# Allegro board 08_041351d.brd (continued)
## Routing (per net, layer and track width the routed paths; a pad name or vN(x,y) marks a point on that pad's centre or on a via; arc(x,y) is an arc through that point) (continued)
VCC-1P35: length 46
  TOP w0.356: C95.1 49.74,19.48 v1(49.63,19.59) ; v1(43.23,40.33) 43.23,40.34 C117.1 ; v1(42.43,38.73) 42.35,38.65 C118.1 ; C116.1 47.87,40.23 v1(47.99,40.36) ; v1(49.63,36.27) 49.78,36.11 C112.1 ; C92.1 49.65,29.89 v1(49.6,29.94) ; C97.1 42.34,19.48 v1(42.43,19.57) ; C94.1 49.78,23.41 v1(49.63,23.57) ; v1(49.63,37.93) 49.71,38.02 C109.1 ; v1(42.43,21.97) 42.35,21.89 C96.1 ; v1(48.83,17.94) 48.88,17.88 C91.1 ; v1(42.43,36.33) 42.34,36.24 C115.1 ; C120.1 v1(41.71,47.48)
  TOP w0.381: 46.34,37.32 v1(45.65,37.32)
  TOP w0.406: C87.1 50.15,28.37 v1(49.63,28.37) ; C86.1 v1(46.66,22.33) ; v1(41.71,48.88) 41.31,48.88 41.06,48.62 R134.2 ; v1(47.8,60.69) v1(48.31,60.69) ; C106.1 v1(45.65,39.73) ; C108.1 v1(45.65,34.91) ; C88.1 v1(45.65,19.41)
  TOP w0.508: 47.3,25.13 v1(46.41,26.02)
  TOP w0.762: C89.1 47.3,25.13
  L15_SIGNAL w0.508: v2(57.08,14.84) v2(57.84,14.84)
  L15_SIGNAL w0.635: v2(57.08,14.84) v2(56.31,14.84) 53.9,14.84 52.88,15.86 49.96,15.86 48.83,16.99 v1(48.83,17.94)
  BOTTOM w0.356: v1(48.83,17.94) 48.83,17.97 U2.A8 ; v1(49.63,36.27) 49.63,36.33 U3.C9 ; v1(43.23,35.59) 43.29,35.59 U3.B2 ; v1(49.63,37.19) 49.56,37.19 U3.D9 ; U2.R9 v1(49.6,29.94) ; U3.A8 48.57,34.98 v1(48.57,34.73) ; v1(49.7,45.05) 49.65,45 49.64,45 49.37,44.73 U3.N9 ; U3.E9 v1(49.63,37.93) ; U2.H9 v1(49.63,23.57) ; v1(43.23,37.07) 43.23,37.13 U3.D2 ; U2.R1 v1(42.43,29.97) ; v1(42.43,28.3) 42.49,28.3 U2.N1 ; U3.R1 v1(42.43,46.73) ; U3.A1 42.43,34.73 v1(42.43,34.67) ; v1(49.84,46.72) 49.82,46.73 49.63,46.73 U3.R9 ; U3.K8 48.83,42.73 v1(48.83,42.83) ; U2.H2 v1(43.23,23.57) ; v1(47.99,40.36) 47.99,40.3 U3.G7 ; U2.N9 v1(49.63,28.37) ; U2.C9 49.6,19.59 v1(49.63,19.59) ; U3.N1 v1(42.43,45.13) ; U3.C1 v1(42.43,36.33) ; U3.H9 v1(49.63,40.33) ; U3.H2 v1(43.23,40.33) ; U2.B2 v1(43.23,18.77) ; U3.K2 v1(43.23,42.73) ; U2.K2 v1(43.23,25.97) ; U2.E9 v1(49.63,21.17) ; U2.C1 v1(42.43,19.57) ; U3.F1 v1(42.43,38.73) ; U2.K8 v1(48.83,25.97) ; U2.A1 v1(42.43,17.97) ; U2.D2 v1(43.23,20.37) ; U2.D9 v1(49.63,20.37) ; U2.F1 v1(42.43,21.97) ; U2.G7 v1(48.03,22.77)
  vias: v1(47.8,61.2) v1(48.31,61.2) v1(53.14,59.67) v1(53.14,59.04) v1(53.14,58.4) v1(53.14,57.77)
VCC-3P3V: length 7.2
  TOP w0.508: E7.2 23.17,59.54 v1(22.53,60.18) 21.86,59.51 C196.1
  BOTTOM w0.203: R221.1 44.46,60.22 44.5,60.22 ; U14.10 45.39,60.22
  BOTTOM w0.254: 45.39,60.22 44.5,60.22
  BOTTOM w0.381: C43.2 v1(45.52,61.2)
  BOTTOM w0.508: v1(42.47,60.31) R222.1 R221.1 ; R178.1 v1(11.86,55.1)
VCC-3P3V-IO: length 83.8
  TOP w0.127: U1.T6 v1(24.34,34.59) ; U1.K6 v1(29.94,34.59) ; U1.R6 v1(25.14,34.59) ; U1.N6 v1(26.74,34.59)
  TOP w0.305: R168.1 v1(34.98,48.62) ; U11.21 7.55,11.54 7.16,11.16 v1(7.16,10.52) ; U15.21 19.8,52.69 19.61,52.88 v1(19.61,53.07) 19.73,53.19 U15.20 ; U11.17 v1(4.64,13.84) ; R167.1 v1(33.33,48.62)
  TOP w0.381: E8.2 31.23,58.59 31.04,58.4 v1(31.04,57.77)
  TOP w0.406: v1(28.75,40.49) 28.75,41.04 C71.1 29.77,41.04 v1(29.77,40.49) ; R169.2 v1(33.83,43.8) ; J3.4 v1(1.98,27.26) ; v1(6.66,10.01) v1(6.66,10.52) v1(7.16,10.52) ; v2(40.06,49.62) 40.31,49.88 40.31,50.36 D4.A
  TOP w0.508: R8.1 42.47,11.54 41.84,10.9 v1(41.84,8.87) ; C41.1 v1(7.16,10.52) ; C197.1 v2(27.99,58.87)
  L3_SIGNAL w0.406: v1(33.83,43.8) 33.33,44.3 v1(33.33,48.62)
  L7_SIGNAL w0.406: v1(41.84,8.87) 41.84,8.24 41.25,7.65 41.23,7.65 40.96,7.38 40.96,6.22 35.79,1.05 27.31,1.05 25.33,3.03 18.47,3.03 16.82,4.68 10.34,4.68 8.18,6.84 8.18,9.51 v1(7.16,10.52)
  L15_SIGNAL w0.406: v1(34.98,48.62) 37.71,48.62 38.72,49.64 40.04,49.64 v2(40.06,49.62)
  BOTTOM w0.406: v1(29.77,40.49) 29.77,41.13 29.35,41.55 C71.1 29.05,41.55 28.75,41.26 v1(28.75,40.49) ; v2(3.23,10.4) 3.74,10.9
  BOTTOM w0.508: 3.74,10.9 R109.1 ; C57.1 v1(3.23,9.25) ; R4.1 v1(3.61,17) C42.1 ; v1(19.61,53.07) 20.03,53.49 C184.1
VCC-BRAM: length 25.2
  TOP w0.127: U1.H10 v1(31.54,31.39) ; U1.G11 v1(32.34,29.79)
  TOP w0.406: v2(54.41,20.56) 55.04,20.56 C56.1 55.68,19.79 55.04,19.16 v2(54.41,19.16) ; v1(39.93,21.57) 40.63,21.57
  L16_SIGNAL w0.406: v2(54.41,20.56) v2(54.41,19.16) 54.92,18.65 54.92,12.94 54.41,12.43 54.41,10.52 54.79,10.14 54.79,9.25 54.03,8.49 54.03,7.47 54.54,6.97 54.54,4.43 v2(54.66,4.3) ; v2(54.66,4.3) v2(55.3,4.3) 55.3,4.05 v2(54.92,3.66) 54.66,3.92 v2(54.66,4.3)
  BOTTOM w0.406: 39.3,21.57 v1(39.93,21.57)
VCCINT-1P0V: length 11.7
  TOP w0.356: U1.H12 v1(31.54,28.99) ; U1.P12 v1(25.94,28.99) ; U1.M12 v1(27.54,28.99) ; U1.L13 v1(28.34,28.19) ; U1.J13 v1(30.74,28.19) ; U1.R13 v1(25.14,28.19) ; U1.G13 v1(32.34,28.19) ; U1.K12 v1(29.94,28.99) ; U1.N13 v1(26.74,28.19)
  TOP w0.406: C141.1 v1(34.72,20.56) ; C23.1 v1(28.63,20.56) ; C19.1 v1(36.25,20.56)
  BOTTOM w0.406: C141.1 v1(35.49,19.79) ; C23.1 v1(29.39,19.79) ; v1(34.85,16.75) 34.89,16.71 C195.1 ; C16.1 v1(27.74,19.79)
  vias: v1(28.5,16.75) v1(29.64,16.75) v1(30.91,16.75) v1(35.61,16.75)
VCCO-DDR: length 10.2
  TOP w0.356: U1.P2 v1(25.94,37.79) ; U1.L3 v1(28.34,36.99) ; U1.G1 v1(32.34,38.59) ; v1(23.53,38.59) 23.93,38.19 U1.U1 ; U1.E5 v1(33.94,35.39) ; U1.H4 v1(31.54,36.19) ; U1.V4 v1(22.74,36.19) ; U1.D2 v1(34.74,37.79) ; U1.R5 v1(25.14,35.39) ; U1.A3 v1(37.14,36.99)
  TOP w0.406: 49.33,1.51 49.49,1.34 C193.1
  TOP w0.508: E2.2 v1(49.52,4.11)
  BOTTOM w0.406: C17.1 v1(25.96,41.76) ; C11.1 v1(32.06,41.76) ; C121.1 v1(34.72,41.76) ; C125.1 v1(38.15,41.76) ; C20.1 v1(23.29,41.76)
  vias: v1(49.46,4.68)
VCCPCOM-1P8V: length 57.9
  TOP w0.305: v1(24.94,49.89) 24.66,50.17 U15.32 ; U15.28 v1(22.66,49.77) ; U15.14 22.16,56.1 ; U15.11 v1(23.66,56.1) ; v1(67.62,52.81) v1(67.62,53.42) 68.12,53.92 68.12,55.13 U13.B4 ; U11.5 v1(10.58,15.34) ; U15.30 v1(23.66,49.78) ; v1(25.96,54.97) 25.68,54.69 U15.8
  TOP w0.356: U1.B6 v1(36.34,34.59) ; U1.F8 v1(33.14,32.99) ; U1.H8 v1(31.54,32.99) ; U1.K8 v1(29.94,32.99) ; U1.G9 v1(32.34,32.19) ; U1.M8 v1(27.54,32.99) ; U1.D12 v1(34.74,28.99) ; v1(36.34,25.79) U1.B16 ; U1.N11 v1(26.74,29.79) ; U1.J11 v1(30.74,29.79) ; U1.A13 v1(37.14,28.19) ; U1.E15 v1(33.94,26.59) ; U1.N9 v1(26.74,32.19) ; U1.R9 v1(25.14,32.19) ; U1.L11 v1(28.34,29.79) ; U1.P10 v1(25.94,31.39) ; U1.D7 v1(34.74,33.79)
  TOP w0.381: v1(10.58,15.34) 10.75,15.17 11.15,15.17 C54.1
  TOP w0.406: C39.1 46.14,4.06 v1(46.14,4.81) Y1.4 ; R37.1 v1(40.06,22.97) ; C53.1 v1(36.25,41.76) ; C179.1 v1(24.69,41.76) ; L12.1 v1(34.24,45.8) ; C175.1 v1(27.36,41.76) ; R194.1 v1(43.36,13.32)
  TOP w0.508: E9.2 14.53,15.16 v1(14.53,15.98) v1(14.53,16.75) ; v1(47.42,52.81) 48.19,52.81 48.48,52.52 S4.3 ; R9.1 v1(22.66,49.09) ; v1(53.65,52.81) 53.94,52.52 S3.3 ; v1(43.11,4.43) 42.6,4.93 R7.1 42.04,5.75 Q5.1 ; C54.1 C55.1 ; E1.1 v1(26.15,49.19)
  TOP w1.27: S1.3 v2(4.45,7.81)
  BOTTOM w0.254: v1(55.3,61.2) 55.3,61.13 C83.1
  BOTTOM w0.305: C83.1 54.73,61.13 v1(54.66,61.2) ; v1(34.74,33.79) 34.82,33.7
  BOTTOM w0.381: v1(24.94,49.89) 24.94,50.4
  BOTTOM w0.406: C32.1 23.66,48.85 v1(23.66,49.78) ; 54.73,57.32 54.24,57.32 v1(54.23,57.31) ; 54.73,57.32 C82.1 ; 54.73,57.32 v1(54.74,57.31) ; 34.82,33.7 R31.1 ; C174.1 v1(38.41,19.79) ; v1(22.66,49.09) 22.66,48.58 C182.1 ; v1(14.53,16.75) v1(14.53,15.98) ; C52.1 v1(37.01,19.79)
  BOTTOM w0.508: v1(65.97,59.8) R28.1 ; 62.28,48.24 v1(62.28,47.61) ; v1(6.28,28.94) 5.26,28.94 4.62,28.3 R36.1 ; R6.1 v1(51.87,60.81) ; R40.1 45.65,4.31 v1(46.14,4.81)
  BOTTOM w0.635: v1(16.56,36.56) 16.44,36.68 C145.2 17.54,38.25 v1(17.96,37.83) ; C181.1 24.94,51.71 24.94,50.4 ; C126.1 v2(19.7,57.55)
  vias: v1(17.96,37.19) v1(21.96,56.24) v1(25.71,55.73) v2(61.65,45.83)
VCCPINT-1P0V: length 11.8
  TOP w0.356: U1.G7 v1(32.34,33.79) ; U1.N7 v1(26.74,33.79) ; U1.R7 v1(25.14,33.79) ; U1.L7 v1(28.34,33.79) ; U1.J7 v1(30.74,33.79) ; U1.P8 v1(25.94,32.99)
  TOP w0.381: C159.1 40.57,35.03 v1(39.93,35.03)
  TOP w0.406: C163.1 v1(39.93,32.11) ; C10.1 v1(39.93,33.89)
  BOTTOM w0.406: C162.1 v1(39.93,35.03)
  BOTTOM w0.508: v1(77.27,3.54) 78.16,2.65 79.05,2.65 C173.1 78.28,4.43 77.65,4.43 v1(77.52,4.3)
  vias: v2(47.17,9.51) v2(47.93,9.51) v2(56.19,8.11) v2(56.95,8.11) v2(57.71,8.11)
VDD_INTERFACE: length 17.8
  TOP w0.127: U17.H12 v1(66.8,34.49)
  TOP w0.254: U22.1 56.94,29.79 57.43,29.31 v1(57.46,29.31)
  TOP w0.305: R306.2 v1(85.27,7.6) ; C245.1 57.39,28.89 57.44,28.93 57.44,29.28 v1(57.46,29.31)
  TOP w0.356: U1.C19 v1(35.54,23.39) ; U1.K20 v1(29.94,22.59) ; U1.F18 v1(33.14,24.19) ; U1.H14 v1(31.54,27.39) ; 30.34,25.39 v1(30.74,24.99) ; U1.M16 v1(27.54,25.79)
  TOP w0.406: C44.1 v1(31.68,20.56) ; C47.1 v1(33.2,20.56) ; C51.1 v1(30.15,20.56) ; v2(85.02,6.2) E10.2 v2(84.25,5.57) ; U1.J17 30.34,25.39
  TOP w0.508: v1(38.28,14.59) 38.79,14.59 39.42,13.95 C28.1 39.8,13.95 ; v1(41.07,13.44) 40.44,13.44 39.93,13.95 39.8,13.95 ; 39.8,13.95 40.31,14.46 v1(41.07,14.46)
  BOTTOM w0.254: C355.1 66.13,34.97 66.57,34.53 66.76,34.53 v1(66.8,34.49) 66.85,34.55 C356.1
  BOTTOM w0.406: C44.1 v1(32.4,19.79) ; C51.1 v1(30.91,19.79) ; C47.1 v1(33.92,19.79)
  vias: v1(61.27,22.9) v1(61.27,22.4) v1(61.77,22.9) v1(61.77,22.4)
VDDA_GPO: length 5
  TOP w0.127: U17.B8 v1(61.2,31.29)
  BOTTOM w0.305: R67.1 77.65,38.21 v1(77.52,38.08)
  BOTTOM w0.356: v1(61.2,31.29) C319.1 61.04,30.69 C360.1
  BOTTOM w0.508: C358.1 v2(86.54,56.75) ; v2(85.9,55.99) 85.27,56.62 E11.2 ; C361.1 v2(86.54,58.4)
VDDA_GPO_PWR: length 80.3
  TOP w0.406: v2(86.29,6.2) E10.1 v2(87.05,5.57)
  L16_SIGNAL w0.635: 87.05,6.33 88.06,7.35 90.73,7.35 91.37,7.98 91.37,9.51 92.25,10.4 92.25,12.49 91.24,13.51 91.24,33.89 91.87,34.53 91.87,45.13 90.1,46.91 v2(90.1,51.1) v2(90.1,51.92) ; 87.05,6.33 v2(87.05,5.57) ; 87.05,6.33 86.92,6.2 v2(86.29,6.2)
  BOTTOM w0.254: U6.2 81.46,58.14 81.69,58.38 81.42,58.64 U6.1
  BOTTOM w0.406: 85.24,58.74 E11.1
  BOTTOM w0.508: 87.57,47.37 JX4.9 ; 85.24,58.74 C200.1 82.89,58.4 82.88,58.4 82.85,58.38 81.69,58.38
  BOTTOM w0.635: 87.57,47.37 88.78,47.37 90.1,48.69 v2(90.1,51.1) v2(90.1,51.92) 90.1,51.99 90.6,52.5 90.6,58.66 89.59,59.67 86.22,59.67 E11.1
1P3_SUPPLY_A: length 54.5
  TOP w0.305: 79.99,12.61 v1(80.06,12.61) 80.26,12.41
  TOP w0.356: U17.J3 v1(67.6,26.49) ; U17.K3 v1(68.4,26.49) ; U17.B9 v1(61.2,32.09) ; U17.E2 v1(63.6,25.69) ; U17.B10 v1(61.2,32.89) ; U17.F2 v1(64.4,25.69)
  TOP w0.381: v1(77.27,9.63) 77.01,9.38 C315.1 ; v1(77.27,9.63) 77.61,9.97 U19.13 ; v1(77.27,9.63) 76.82,10.08 C314.1 ; v1(77.27,9.63) 77.58,9.32 U19.14 ; v1(78.5,12.72) 78.96,12.26 U19.12 ; U19.11 79.61,12.23 79.99,12.61 ; 81.33,11.53 80.91,11.11 U19.9 ; U19.10 80.26,12.41
  TOP w0.508: C312.1 81.17,12.59 ; 81.17,12.59 81.33,12.43 81.33,11.53 81.71,11.15 v1(81.71,10.65) ; 81.17,12.59 81.15,12.61 v1(80.06,12.61) ; C313.1 v1(78.5,12.72)
  TOP w0.635: v2(79.48,47.5) v1(78.82,47.5) 78.03,46.72 74.22,46.72 73.39,47.54 67.55,47.54 65.08,45.07 65.08,39.86 v1(61.01,35.8)
  BOTTOM w0.33: U24.18 78.94,44.94 79.48,45.47 79.48,46.57
  BOTTOM w0.356: C329.1 68.24,26.33 v1(68.4,26.49) ; v1(64.4,25.69) 64.28,25.57 C322.1 63.72,25.57 v1(63.6,25.69) ; v1(61.2,32.89) 61.33,32.76 C321.1 61.33,32.23 v1(61.2,32.09) ; C326.1 67.44,26.33 v1(67.6,26.49)
  BOTTOM w0.406: C327.1 v1(61.01,35.8) ; C323.1 69.68,22.42 v2(69.68,22.99) 69.68,23.58 C320.1
  BOTTOM w0.508: v2(68.12,22.84) 68.12,22.08 C328.1
  BOTTOM w0.635: v1(78.82,47.5) v2(79.48,47.5) 79.48,46.57
1P3_SUPPLY_B: length 67.5
  TOP w0.254: 86.79,10.4 v1(86.92,10.27) ; 86.79,9.63 v1(86.92,9.51)
  TOP w0.305: L1.1 v1(68.88,35.87) ; 89.91,11.86 v1(90.26,12.21)
  TOP w0.356: C343.1 86.79,10.4 ; C344.1 86.79,9.63 ; U17.A9 v1(60.4,32.09) ; U17.K4 v1(68.4,27.29) ; U17.A8 v1(60.4,31.29) ; U17.F12 v1(64.4,34.49) ; U17.D3 v1(62.8,26.49) ; U17.A7 v1(60.4,30.49) ; U17.E3 v1(63.6,26.49) ; U17.D2 v1(62.8,25.69) ; v1(60.4,32.89) U17.A10
  TOP w0.381: U20.13 87.22,9.97 v1(86.92,10.27) ; L9.1 v1(71.74,28.74) ; v1(90.26,12.21) 90.56,11.91 U20.9 ; U20.12 88.61,11.75 v1(88.32,12.05) 88.28,12.08 ; U20.14 87.1,9.32 v1(86.92,9.51) ; L8.1 71.3,31.45 v1(71.3,31.73) ; L2.1 v1(72.49,35.87) ; U20.10 89.91,11.86 ; U20.11 v1(89.26,11.99)
  TOP w0.508: C341.1 v1(90.26,12.21) ; C342.1 88.28,12.08
  L9_POWER w0.203: v1(64.4,34.49) 64.4,35.08 v1(63.68,35.8) ; 61.77,39.48 61.77,36.3 v1(62.28,35.8) 61.77,35.29 61.27,35.29 60.79,34.81 60.79,33.29 v1(60.4,32.89) v1(60.4,32.09) ; 63.2,21.98 63.2,25.29 v1(62.8,25.69) v1(62.8,26.49) ; 64.19,21.95 64.19,24.3 64,24.49 64,26.09 v1(63.6,26.49) ; v1(59.23,27.54) 59.23,29.33 v1(60.4,30.49) v1(60.4,31.29) ; v1(68.4,27.29) 68.38,27.29 68,26.91 68,25.38 67.77,25.15 v2(67.77,24.64)
  L9_POWER w0.254: 63.3,39.35 63.3,36.18 v1(63.68,35.8) ; 62.66,21.57 60.06,21.57 59.23,22.4 v1(59.23,27.54) ; v2(67.77,24.64) 67.77,24.09 69.52,22.33
  BOTTOM w0.254: C330.1 64.43,34.53 v1(64.4,34.49)
  BOTTOM w0.33: U24.19 79.36,44.44 80.11,45.19 v1(80.11,45.32)
  BOTTOM w0.356: C334.1 62.67,26.37 v1(62.8,26.49) ; C325.1 60.38,30.47 v1(60.4,30.49) ; v1(68.4,27.29) 68.4,27.27 C333.1
  BOTTOM w0.406: C335.1 v1(63.68,35.8) ; C332.1 v1(62.28,35.8)
  BOTTOM w0.508: C324.1 68,23.92 68,24.42 v2(67.77,24.64)
  BOTTOM w0.635: 58.47,27.54 v1(59.23,27.54)
  vias: v1(74.16,29.76) v1(74.16,29.32) v1(74.6,29.76) v1(74.6,29.32) v2(65.97,37.07) v2(66.6,37.07) v2(67.24,37.07)
AD9364_CLK: length 48.4
  TOP w0.14: C62.1 74.16,57 v1(73.84,57)
  L16_SIGNAL w0.095: v1(89.9,29.76) 90.48,30.33 90.48,33.95 88.51,35.92 88.51,44.11 89.33,44.94 89.33,45.76 88.9,46.2 88.9,50.17 87.45,51.62 82.27,51.62 77.9,55.99 74.86,55.99 v1(73.84,57)
  BOTTOM w0.14: v1(73.84,57) 73.27,57 R5.1 ; v1(89.9,29.76) 89.59,29.45 89.59,27.59 87.77,25.77 JX4.63
ADP2114_VIN: length 8.2
  TOP w0.305: v2(72.32,2.52) 71.05,2.52 70.09,3.48 U4.10 ; U4.8 68.73,1.66 v1(68.89,1.51) 68.82,1.44 R23.2 ; v1(66.85,1.51) 66.73,1.63 U4.4 ; U4.31 v2(63.48,3.48)
  TOP w0.406: C146.1 v2(62.41,1.89) ; C150.1 v2(62.66,2.9)
AUXADC: length 34.8
  TOP w0.127: U17.L5 v1(69.2,28.09)
  L16_SIGNAL w0.095: v1(69.2,28.09) 69.56,27.73 73.97,27.73 75.74,29.51 75.74,31.22 78.72,34.2 78.72,35.01 81.71,38.01 81.71,44.49 86.09,48.88 v1(87.3,48.88)
  BOTTOM w0.14: v1(87.3,48.88) 87.3,48.35 87.12,48.17 JX4.7
AUXDAC1: length 38.8
  TOP w0.127: U17.B3 v1(61.2,26.49)
  L16_SIGNAL w0.095: v1(61.2,26.49) 61.2,26.47 61.52,26.14 62.16,26.14 62.46,26.45 62.46,26.63 62.66,26.83 62.84,26.83 62.89,26.88 64.92,26.88 65.46,27.41 65.46,28.18 65.76,28.48 70.27,28.48 70.66,28.87 70.66,29.45 72.7,31.48 72.7,33 73.9,34.21 75.74,34.21 77.09,35.55 77.09,36.33 77.97,37.21 77.97,38.53 81.27,41.83 81.27,46.46 v1(82.98,48.17)
  BOTTOM w0.14: JX4.8 v1(82.98,48.17)
AUXDAC2: length 36.1
  TOP w0.127: U17.C3 v1(62,26.49)
  L16_SIGNAL w0.095: v1(62,26.49) 62,26.77 62.36,27.13 62.36,27.46 62.59,27.69 64.72,27.69 65.08,28.05 65.08,28.56 65.84,29.32 70.03,29.32 72.32,31.6 72.32,33.26 73.78,34.72 74.86,34.72 77.14,37 77.14,39.61 79.3,41.76 80.44,41.76 80.82,42.15 80.82,47.02 v1(80.24,47.61)
  BOTTOM w0.14: v1(80.24,47.61) 80.57,47.61 80.81,47.37 JX4.10
CARRIER_RESET: length 64.3
  TOP w0.14: Q5.3 42.98,10.01 43.87,10.9 R8.2 v1(43.87,12.43)
  L3_SIGNAL w0.095: v1(32.73,49.55) 33.45,50.27 37.72,50.27 39.75,48.24 44.63,48.24 45,47.87 46.52,47.87 46.99,48.34 49.4,48.34 49.89,47.86 v1(50.47,47.86)
  L16_SIGNAL w0.095: v1(43.87,12.43) 46.28,12.43 46.79,12.94 46.79,17.63 47.68,18.52 48.1,18.52 48.69,19.1 48.89,19.1 49.07,19.29 49.45,19.29 49.49,19.25 49.93,19.25 50.47,19.79 v1(50.47,47.86)
  BOTTOM w0.14: JX1.6 v1(32.73,49.55)
COMP_1P8V: length 6.6
  TOP w0.14: U4.2 65.73,1.91 65.33,1.51 v1(65.33,1)
  BOTTOM w0.14: v1(65.33,1) 62.39,1 62.14,1.25 R46.1 C67.1
COMP_1P35V: length 3.7
  TOP w0.14: U4.7 v1(68.23,1.31)
  BOTTOM w0.14: v1(68.23,1.31) 68.44,1.53 68.44,2.08 C68.1 69.14,2.01 C114.1
CTRL_IN0: length 5.8
  TOP w0.127: U17.C5 v1(62,28.09)
  TOP w0.14: v1(58.73,30.21) 58.46,30.48 U22.2
  L12_SIGNAL w0.095: v1(62,28.09) 61.66,28.43 60.12,28.43 58.73,29.83 v1(58.73,30.21)
CTRL_IN1: length 6.8
  TOP w0.127: U17.C6 v1(62,28.89)
  TOP w0.14: U22.3 58.59,30.98 v1(58.73,30.84)
  L12_SIGNAL w0.095: v1(58.73,30.84) 58.73,30.97 58.98,31.22 59.99,31.22 60.26,30.95 61.06,30.95 61.98,30.03 62.14,30.03 62.34,29.83 62.34,29.23 v1(62,28.89)
CTRL_IN2: length 6.9
  TOP w0.127: U17.D5 v1(62.8,28.09)
  TOP w0.14: U22.4 58.6,31.48 59.09,30.99 59.09,30.99 v1(59.23,30.84)
  L12_SIGNAL w0.095: v1(59.23,30.84) 59.36,30.84 60.38,29.83 60.89,29.83 61.66,29.05 61.66,28.75 61.75,28.66 61.98,28.43 62.14,28.43 62.48,28.09 v1(62.8,28.09)
CTRL_IN3: length 7.6
  TOP w0.127: U17.D6 v1(62.8,28.89)
  TOP w0.14: U22.5 v1(58.72,31.98)
  L12_SIGNAL w0.095: v1(58.72,31.98) 59.75,31.98 60.1,31.63 61.34,31.63 61.54,31.43 61.54,31.15 61.86,30.83 62.14,30.83 62.34,30.63 62.34,30.28 62.79,29.83 62.79,28.9 v1(62.8,28.89)
DDR3_A0: length 57.7
  TOP w0.197: R136.1 45.2,45.45 44.34,45.45 v1(44.03,45.13) ; U1.N2 v1(26.74,37.79)
  L6_SIGNAL w0.14: v1(44.03,45.13) 44.5,44.65 44.5,44.29 44.18,43.97 43.95,43.97 43.66,43.68 43.66,43.46 43.38,43.17 43.11,43.17 42.85,42.91 42.85,35.41 43.24,35.03 43.38,35.03 43.59,34.82 43.59,34.17 45.72,32.04 45.72,29.65 44.37,28.3 v1(44.03,28.3)
  L7_SIGNAL w0.14: v1(44.03,28.3) 47.3,28.3 47.68,27.92 47.4,26.89 47.31,26.61 47.07,26.4 41.07,26.4 40.31,27.16 40.31,27.16 37.76,29.71 37.76,30.09 37.44,30.42 31.04,30.42 30.3,31.16 30.3,31.54 30.09,31.75 29.66,31.75 28.96,32.45 28.7,32.72 28.7,33.14 28.49,33.35 28.19,33.35 27.9,33.64 27.9,33.94 27.69,34.15 27.39,34.15 27.1,34.44 27.1,34.78 26.85,35.03 26.59,35.03 26.37,35.24 26.37,36.34 26.59,36.55 26.81,36.55 27.07,36.81 27.1,36.81 27.1,37.14 26.74,37.5 v1(26.74,37.79)
  BOTTOM w0.197: U2.N3 44.09,28.3 v1(44.03,28.3) ; U3.N3 v1(44.03,45.13)
DDR3_A1: length 56
  TOP w0.197: U1.K2 v1(29.94,37.79) ; v1(48.03,45.93) 47.17,46.79 47.17,47.21 47,47.38 46.83,47.38 R137.1
  L12_SIGNAL w0.14: v1(48.03,45.93) 47.27,45.93 46.77,45.43 46.51,45.43 46.3,45.22 46.3,44.96 46.2,44.86 46.2,31.06 v1(48.03,29.23)
  L13_SIGNAL w0.14: v1(29.94,37.79) 30.11,37.79 30.47,38.15 30.89,38.15 31.1,37.94 31.1,37.64 31.39,37.35 31.69,37.35 31.9,37.14 31.9,36.84 32.19,36.55 32.49,36.55 32.7,36.34 32.7,36.04 32.99,35.75 33.28,35.75 33.57,35.46 33.57,34.44 33.86,34.15 34.09,34.15 34.37,33.86 34.37,33.64 34.59,33.43 35.39,33.43 36.19,33.43 38.36,33.43 38.38,33.4 38.68,33.4 38.71,33.43 40.57,33.43 40.69,33.55 40.69,33.89 40.82,34.02 41.58,34.02 41.71,33.89 41.71,33.55 41.84,33.43 44.76,33.43 44.88,33.3 44.88,32.87 45.01,32.75 45.52,32.75 45.65,32.62 45.65,32.11 45.52,31.99 45.01,31.99 44.88,31.86 44.88,31.35 44.76,31.22 41.96,31.22 41.71,30.97 41.71,30.21 42.06,29.85 42.06,29.82 42.28,29.6 47.65,29.6 v1(48.03,29.23)
  BOTTOM w0.197: U3.P7 v1(48.03,45.93) ; U2.P7 48.03,29.17 v1(48.03,29.23)
DDR3_A2: length 58.2
  TOP w0.197: v1(44.03,45.87) 44.37,46.21 45.2,46.21 R138.1 ; U1.M3 v1(27.54,36.99)
  L6_SIGNAL w0.14: v1(44.03,29.23) 44.29,29.23 45.19,30.13 45.19,31.42 43.31,33.29 42.6,33.29 41.62,34.27 41.62,42.82 42.22,43.42 42.22,43.42 42.24,43.43 42.61,43.43 43.08,43.89 43.3,43.89 43.66,44.26 43.66,45.28 44.03,45.64 v1(44.03,45.87)
  L13_SIGNAL w0.14: v1(27.54,36.99) 27.54,36.68 27.41,36.56 26.5,36.56 26.37,36.68 26.37,38.88 26.98,39.48 28.37,39.48 29.57,38.28 29.57,36.84 29.86,36.55 30.09,36.55 30.37,36.26 30.37,36.04 30.66,35.75 30.89,35.75 31.17,35.47 31.17,32.75 31.36,32.55 34.09,32.55 34.37,32.26 34.37,32.04 34.59,31.83 37.29,31.83 37.44,31.99 37.9,31.99 38.15,32.24 38.15,32.61 38.28,32.73 38.55,32.73 38.66,32.62 38.66,32.11 38.79,31.99 39.04,31.99 39.17,32.11 39.17,32.61 39.3,32.73 39.49,32.73 39.59,32.64 39.59,32.38 39.47,32.26 39.47,32.06 39.57,31.97 39.57,31.73 39.8,31.5 39.8,30.97 41.2,29.57 41.2,28.43 41.83,27.79 42.14,27.79 42.28,27.93 42.58,27.93 42.71,27.79 42.94,27.79 43.08,27.93 43.1,27.93 43.11,27.94 43.38,27.94 43.59,28.15 43.59,28.4 43.61,28.43 43.61,28.82 v1(44.03,29.23)
  BOTTOM w0.197: v1(44.03,29.23) 44.03,29.17 U2.P3 ; v1(44.03,45.87) 44.09,45.87 U3.P3
DDR3_A3: length 57.7
  TOP w0.197: R139.1 41.21,45.52 42.59,45.52 42.98,45.13 v1(43.23,45.13) ; U1.K3 v1(29.94,36.99)
  L6_SIGNAL w0.14: v1(43.23,28.3) 43.23,28.72 43.59,29.08 43.59,29.11 43.66,29.19 43.66,29.38 43.89,29.6 44.18,29.6 44.92,30.35 44.92,31.3 43.2,33.03 42.33,33.03 41.35,34 41.35,43.03 42.24,43.92 42.6,43.92 42.85,44.18 42.85,44.43 42.86,44.44 42.86,44.48 43.23,44.84 v1(43.23,45.13)
  L13_SIGNAL w0.14: v1(43.23,28.3) 42.91,28.62 42.91,28.75 42.78,28.88 42.65,28.88 42.58,28.8 42.42,28.8 42.04,28.43 41.84,28.43 41.71,28.56 41.71,29.57 41.2,30.08 41.2,30.84 41.07,30.97 40.44,30.97 40.31,31.1 40.31,31.35 40.57,31.6 40.57,32.49 40.69,32.62 41.71,32.62 41.84,32.49 41.84,31.86 42.09,31.6 42.85,31.6 42.98,31.73 42.98,32.49 43.11,32.62 43.61,32.62 43.74,32.49 43.74,31.73 43.87,31.6 44.12,31.6 44.38,31.86 44.38,32.75 44.12,33 38.15,33 37.77,32.62 34.6,32.62 34.59,32.63 34.59,32.63 34.37,32.84 34.37,33.06 34.09,33.35 32.19,33.35 31.9,33.64 31.9,35.54 31.61,35.83 31.39,35.83 31.17,36.04 31.17,36.76 31.1,36.84 31.1,37.14 30.89,37.35 30.31,37.35 29.95,36.99 v1(29.94,36.99)
  BOTTOM w0.197: v1(43.23,28.3) 43.29,28.3 U2.N2 ; U3.N2 v1(43.23,45.13)
DDR3_A4: length 56.3
  TOP w0.197: v1(48.83,45.93) 49.22,46.33 50.16,46.33 R140.1 ; U1.M4 v1(27.54,36.19)
  L6_SIGNAL w0.14: v1(48.83,29.23) 49.18,29.58 49.75,29.58 49.96,29.79 49.96,29.95 51.88,31.87 51.88,39.48 52.84,40.43 52.84,43.21 52.01,44.03 52.01,44.03 49.99,46.06 49.99,46.08 49.78,46.29 49.75,46.29 49.71,46.34 49.23,46.34 v1(48.83,45.93)
  L7_SIGNAL w0.14: v1(48.83,29.23) 48.44,29.62 48.44,31.1 48.69,31.35 49.58,31.35 49.84,31.6 49.84,33.38 49.12,34.1 45.44,34.1 45.27,34.27 42.22,34.27 40.29,36.2 40.29,36.45 39.32,37.43 32.99,37.43 32.7,37.72 32.7,37.94 32.49,38.15 29.71,38.15 29.01,37.45 29.01,36.94 28.62,36.55 28.19,36.55 27.82,36.19 v1(27.54,36.19)
  BOTTOM w0.197: v1(48.83,29.23) 48.83,29.17 U2.P8 ; U3.P8 v1(48.83,45.93)
DDR3_A5: length 59.2
  TOP w0.197: v1(43.23,45.87) 42.76,46.34 R141.1 ; U1.L1 v1(28.34,38.59)
  L6_SIGNAL w0.14: v1(43.23,29.23) 43.23,29.45 43.59,29.82 43.59,30.18 43.81,30.4 44.18,30.4 44.39,30.62 44.39,31.08 42.98,32.49 41.71,32.49 40.82,33.38 40.82,45.19 41.49,45.87 41.98,45.87 42.28,45.57 42.58,45.57 42.87,45.87 v1(43.23,45.87)
  L7_SIGNAL w0.14: v1(28.34,38.59) 27.95,38.97 25.71,38.97 25.69,38.96 24.8,38.96 24.7,38.85 24.7,38.33 24.82,38.21 25.33,38.21 25.45,38.34 25.68,38.34 25.79,38.23 25.82,38.23 25.83,38.21 26.09,38.21 26.21,38.34 26.47,38.34 26.6,38.21 27.74,38.21 27.9,38.05 27.9,36.84 27.61,36.55 27.39,36.55 27.17,36.34 27.17,36.04 27.46,35.75 28.58,35.75 29.39,36.56 29.39,37.07 29.67,37.35 30.89,37.35 31.17,37.06 31.17,36.84 31.46,36.55 31.69,36.55 31.97,36.26 31.97,36.04 32.26,35.75 32.49,35.75 32.77,35.46 32.77,34.32 32.94,34.15 38.91,34.15 39.68,33.38 40.18,33.38 41.44,32.13 41.44,31.74 41.85,31.34 41.85,31.34 41.98,31.21 42.6,31.21 42.79,31.02 42.79,30.52 42.99,30.33 43.46,30.33 43.59,30.2 43.59,29.82 43.23,29.45 v1(43.23,29.23)
  BOTTOM w0.197: v1(43.23,29.23) 43.23,29.17 U2.P2 ; v1(43.23,45.87) 43.29,45.87 U3.P2
DDR3_A6: length 59.1
  TOP w0.197: U1.L4 v1(28.34,36.19) ; R143.1 50.28,47.23 49.87,47.23 49.79,47.14 49.24,47.14 48.9,46.79 v1(48.83,46.79)
  L6_SIGNAL w0.14: v1(48.83,29.9) 49.33,30.4 49.78,30.4 49.9,30.53 49.9,30.53 51.61,32.24 51.61,39.99 51.99,40.36 51.99,40.88 51.61,41.26 51.61,43.46 51.38,43.69 51.08,43.69 50.87,43.9 50.87,44.28 50.06,45.1 50.06,45.2 49.85,45.41 49.11,45.41 48.95,45.57 48.68,45.57 48.46,45.78 48.46,46.43 v1(48.83,46.79)
  L13_SIGNAL w0.14: v1(28.34,36.19) 28.34,35.9 28.75,35.48 28.75,30.46 29.57,29.64 29.57,29.64 29.79,29.43 37.41,29.43 42.85,23.98 47.42,23.98 47.92,24.48 48.18,24.48 48.5,24.8 48.98,24.8 49.19,25.02 49.19,25.49 49.2,25.51 49.2,29.53 v1(48.83,29.9)
  BOTTOM w0.197: U2.R8 48.76,29.9 v1(48.83,29.9) ; U3.R8 48.83,46.73 v1(48.83,46.79)
DDR3_A7: length 58.7
  TOP w0.197: v1(43.23,46.79) 42.84,47.18 42.84,47.75 42.6,47.99 R144.1 ; U1.K4 v1(29.94,36.19)
  L6_SIGNAL w0.14: v1(43.23,29.97) 43.22,29.97 42.78,30.4 42.28,30.4 42.06,30.62 42.06,31.12 39.55,33.64 39.55,42.27 39.31,42.5 39.31,42.8 39.55,43.04 39.55,45.45 39.7,45.59 39.7,45.6 39.91,45.81 39.91,45.81 40.08,45.98 40.21,45.98 41.33,47.1 42.92,47.1 v1(43.23,46.79)
  L7_SIGNAL w0.14: v1(43.23,29.97) 42.83,29.57 41.83,29.57 40.07,31.34 39.94,31.34 39.8,31.48 39.68,31.48 37.99,33.17 37.99,33.35 38.22,33.57 38.4,33.57 39.04,32.93 39.04,32.62 39.17,32.49 39.55,32.49 39.77,32.71 39.97,32.71 40.57,32.11 40.57,31.99 40.31,31.73 40.31,31.6 40.64,31.28 40.69,31.28 41.84,30.14 42.02,30.14 42.19,30.31 42.19,30.49 41.26,31.41 41.26,31.42 41.17,31.51 41.17,32.01 40.12,33.06 39.61,33.06 38.79,33.88 37.76,33.88 37.64,33.76 37.64,33.51 37.52,33.38 37.01,33.38 36.88,33.51 36.57,33.51 36.44,33.38 36.19,33.38 36.06,33.51 35.87,33.51 35.74,33.38 35.43,33.38 35.18,33.64 35.1,33.64 34.85,33.38 34.64,33.38 34.59,33.43 34.59,33.43 34.42,33.6 34.25,33.6 34.09,33.43 34.01,33.43 33.96,33.38 33.83,33.38 33.79,33.43 33.79,33.43 33.58,33.63 33.49,33.63 33.26,33.4 33.26,33.38 33.03,33.38 32.77,33.64 32.77,33.86 32.49,34.15 32.26,34.15 31.97,34.44 31.97,34.78 32.12,34.92 32.12,35.09 31.97,35.24 31.97,35.46 31.69,35.75 31.34,35.75 31.17,35.92 31.17,36.27 30.88,36.56 30.66,36.56 30.59,36.63 30.59,36.63 30.44,36.77 30.24,36.77 30.15,36.68 30.14,36.68 30.09,36.63 29.84,36.63 29.64,36.43 29.64,36.29 29.78,36.15 29.9,36.15 v1(29.94,36.19)
  BOTTOM w0.197: v1(43.23,46.79) 43.23,46.73 U3.R2 ; U2.R2 v1(43.23,29.97)
DDR3_A8: length 57.9
  TOP w0.197: v1(48.83,47.53) 49.2,47.9 49.2,48.3 R145.1 ; U1.K1 v1(29.94,38.59)
  L6_SIGNAL w0.14: v1(48.83,30.83) 48.83,31.1 50.99,33.27 50.99,42.26 49.41,43.84 49.41,43.85 49.04,44.21 47.89,44.21 47.31,44.8 47.31,46.86 47.61,47.15 48.45,47.15 v1(48.83,47.53)
  L7_SIGNAL w0.14: v1(48.83,30.83) 49.32,30.33 50.74,30.33 51.49,31.08 51.49,32.62 51.74,32.87 53.14,32.87 53.27,33 53.27,33.89 53.14,34.02 50.22,34.02 49.84,34.4 48.75,34.4 48.72,34.37 45.55,34.37 44.88,35.03 42.09,35.03 38.91,38.21 33.77,38.21 33.71,38.15 33,38.15 32.7,38.46 32.7,38.74 32.49,38.95 30.3,38.95 v1(29.94,38.59)
  BOTTOM w0.197: U3.T8 v1(48.83,47.53) ; U2.T8 48.83,30.77 v1(48.83,30.83)
DDR3_A9: length 57.6
  TOP w0.197: R146.1 45.14,47.23 44.7,46.79 v1(44.03,46.79) ; U1.J4 v1(30.74,36.19)
  L6_SIGNAL w0.14: v1(44.03,46.79) 43.99,46.76 43.99,46.34 43.89,46.23 43.88,46.23 43.66,46.02 43.66,45.79 43.38,45.5 43.16,45.5 43.15,45.49 43.08,45.49 42.86,45.28 42.86,45.21 42.79,45.13 42.79,44.98 42.58,44.77 42.28,44.77 41.98,45.07 41.33,45.07 41.09,44.83 41.09,33.89 42.22,32.76 43.09,32.76 44.65,31.19 44.65,30.51 44.29,30.14 44.2,30.14 v1(44.03,29.97)
  L7_SIGNAL w0.14: v1(30.74,36.19) 30.74,35.9 31.1,35.54 31.1,34.52 31.46,34.15 31.69,34.15 31.97,33.86 31.97,33.64 32.26,33.35 32.49,33.35 32.77,33.06 32.77,32.84 32.99,32.63 33.19,32.63 33.2,32.62 38.1,32.62 39.65,31.07 39.95,31.07 42.34,28.68 42.89,28.68 43.08,28.87 44.5,28.87 44.63,28.99 44.63,29.7 44.76,29.83 44.98,29.83 45.11,29.7 45.11,28.68 45.22,28.57 45.53,28.57 45.65,28.68 45.65,30.33 45.77,30.46 46.03,30.46 46.15,30.33 46.15,28.81 46.28,28.68 46.79,28.68 46.92,28.81 46.92,29.19 46.66,29.45 46.66,30.08 46.92,30.33 46.92,30.78 46.74,30.96 44.63,30.96 44.5,30.83 44.5,30.08 44.39,29.97 v1(44.03,29.97)
  BOTTOM w0.197: v1(44.03,46.79) 44.03,46.73 U3.R3 ; U2.R3 v1(44.03,29.97)
DDR3_A10: length 53.5
  TOP w0.197: U1.F5 v1(33.14,35.39) ; v1(48.03,43.53) 48.42,43.92 48.57,43.92 48.62,43.98 49.35,43.98 49.46,43.86 49.97,43.86 R147.1
  L7_SIGNAL w0.14: v1(48.03,26.7) 48.53,27.2 49.78,27.2 49.99,27.42 49.99,27.42 50.09,27.52 50.09,28.05 50.34,28.3 50.98,28.3 51.23,28.05 51.23,27.52 51.49,27.27 51.74,27.27 52,27.52 52,28.41 51.74,28.66 49.84,28.66 49.78,28.73 48.02,28.73 47.4,29.35 47.4,30.68 46.85,31.22 43.36,31.22 43.11,31.48 42.09,31.48 41.71,31.86 41.71,32.87 39.91,34.67 39.78,34.67 39.42,35.03 37.29,35.03 37.29,35.03 33.79,35.03 33.42,35.39 v1(33.14,35.39)
  L12_SIGNAL w0.14: v1(48.03,43.53) 48.44,43.12 48.44,41.7 48.53,41.6 48.68,41.45 48.75,41.45 48.96,41.24 49.72,41.24 50.2,40.76 50.2,28.18 49.96,27.93 49.58,27.93 49.58,27.93 49.48,27.93 49.26,27.72 49.26,27.61 49.22,27.57 49.22,27.51 48.98,27.27 48.59,27.27 v1(48.03,26.7)
  BOTTOM w0.152: U3.L7 v1(48.03,43.53)
  BOTTOM w0.197: v1(48.03,26.7) 47.96,26.7 U2.L7
DDR3_A11: length 58.8
  TOP w0.197: R148.1 47.17,48.24 47.55,47.86 47.55,47.27 v1(48.03,46.79) ; U1.G4 v1(32.34,36.19)
  L6_SIGNAL w0.14: v1(48.03,29.9) 48.59,30.47 48.98,30.47 49.19,30.68 49.19,30.96 51.26,33.03 51.26,40.01 51.72,40.47 51.72,40.77 51.26,41.23 51.26,43.14 50.43,43.97 50.43,44.1 49.91,44.61 49.08,44.61 48.95,44.48 48,44.48 47.58,44.91 47.58,46.34 48.03,46.79 v1(48.03,46.79)
  L7_SIGNAL w0.14: v1(48.03,29.9) 47.66,30.26 47.66,30.98 47.68,30.99 47.68,31.48 47.42,31.73 45.77,31.73 45.52,31.99 45.52,33.38 45.39,33.51 45.14,33.51 45.01,33.38 45.01,31.73 44.88,31.6 44.63,31.6 44.5,31.73 44.5,33.5 44.38,33.62 44.12,33.62 43.99,33.5 43.99,31.73 43.87,31.6 43.61,31.6 43.49,31.73 43.49,33.26 43.36,33.38 43.1,33.38 42.85,33.13 42.85,32.49 42.98,32.37 42.98,31.98 42.75,31.75 42.45,31.75 42.09,32.11 42.09,33.17 40.29,34.97 40.29,35.18 40.08,35.39 39.86,35.39 39.51,35.75 38.79,35.75 38.66,35.88 38.66,35.92 38.53,36.05 37.9,36.05 37.77,35.92 37.77,35.88 37.64,35.75 33.06,35.75 32.74,36.07 32.74,37.14 32.53,37.35 32.19,37.35 31.97,37.14 31.97,36.82 32.34,36.46 v1(32.34,36.19)
  BOTTOM w0.197: v1(48.03,46.79) 48.03,46.73 U3.R7 ; U2.R7 47.96,29.9 v1(48.03,29.9)
DDR3_A12: length 51.6
  TOP w0.197: v1(48.03,45.13) 46.79,46.37 46.79,46.65 R149.1 ; U1.E4 v1(33.94,36.19)
  L12_SIGNAL w0.14: v1(48.03,28.3) 48.46,28.74 48.46,30.98 48.57,31.08 48.57,31.99 48.06,32.49 47.3,32.49 47.17,32.62 47.17,39.99 47.28,40.1 47.28,40.4 47.17,40.52 47.17,44.69 47.61,45.13 v1(48.03,45.13)
  L13_SIGNAL w0.14: v1(33.94,36.19) 33.94,36.4 34.08,36.55 34.89,36.55 35.1,36.34 35.1,36.18 35.17,36.11 35.17,35.24 35.39,35.03 38.91,35.03 39.3,35.41 41.58,35.41 41.96,35.03 44.5,35.03 46.79,32.75 49.46,32.75 49.84,32.37 49.84,31.49 49.27,30.92 49.27,30.76 48.98,30.47 48.83,30.47 48.44,30.08 48.44,27.54 48.19,27.29 46.53,27.29 46.28,27.54 46.28,28.05 46.53,28.3 v1(48.03,28.3)
  BOTTOM w0.197: U2.N7 47.96,28.3 v1(48.03,28.3) ; U3.N7 v1(48.03,45.13)
DDR3_A13: length 54.7
  TOP w0.197: R150.1 44.63,48.69 44.63,47.78 44.38,47.53 v1(44.03,47.53) ; U1.D4 v1(34.74,36.19)
  L6_SIGNAL w0.14: v1(44.03,30.77) 44.03,30.81 43.11,31.73 41.84,31.73 40.45,33.12 40.45,43.3 40.55,43.39 40.55,43.69 40.45,43.79 40.45,45.59 41.09,46.23 42.21,46.23 42.28,46.29 42.58,46.29 42.64,46.23 43.17,46.23 43.66,46.72 43.66,46.94 44.03,47.3 v1(44.03,47.53)
  L13_SIGNAL w0.14: v1(44.03,30.77) 44.45,30.77 45.26,29.95 47.17,29.95 47.42,30.21 47.42,30.46 47.17,30.72 45.52,30.72 45.26,30.97 45.26,31.22 45.65,31.6 48.98,31.6 49.2,31.83 49.2,32.14 48.98,32.37 46.53,32.37 44.6,34.3 42.28,34.3 42.18,34.4 39.55,34.4 39.3,34.15 34.66,34.15 34.34,34.47 34.34,35.8 v1(34.74,36.19)
  BOTTOM w0.197: U2.T3 v1(44.03,30.77) ; U3.T3 v1(44.03,47.53)
DDR3_A14: length 55.6
  TOP w0.197: U1.F4 v1(33.14,36.19) ; R151.1 47.11,48.94 48.03,48.02 v1(48.03,47.53)
  L6_SIGNAL w0.14: v1(48.03,30.83) 50.73,33.53 50.73,42.15 49.15,43.73 49.15,43.74 48.93,43.95 48.63,43.95 48.58,43.89 47.84,43.89 47.04,44.69 47.04,47.1 47.47,47.53 v1(48.03,47.53)
  L7_SIGNAL w0.14: v1(48.03,30.83) 48.06,30.86 48.06,31.35 48.31,31.6 48.57,31.6 48.58,31.62 49.2,31.62 49.46,31.87 49.46,32.24 49.2,32.49 49.2,33 49.46,33.26 49.46,33.39 49.08,33.76 48.82,33.76 48.69,33.64 48.69,32.25 48.55,32.11 48.27,32.11 48.13,32.25 48.13,33.64 48.01,33.76 47.7,33.76 47.58,33.64 47.58,32.25 47.44,32.11 47.16,32.11 47.02,32.25 47.02,33.64 46.89,33.76 46.59,33.76 46.46,33.64 46.46,32.25 46.32,32.11 46.04,32.11 45.9,32.25 45.9,33.64 45.7,33.83 45.33,33.83 45.27,33.89 43.23,33.89 42.83,33.48 42.47,33.48 40.01,35.94 39.78,35.94 39.17,36.56 38.79,36.56 38.53,36.81 37.9,36.81 37.64,36.56 33.5,36.56 v1(33.14,36.19)
  BOTTOM w0.197: v1(48.03,30.83) 48.03,30.77 U2.T7 ; U3.T7 v1(48.03,47.53)
DDR3_BA0: length 57.4
  TOP w0.197: v1(43.23,44.33) 43,44.56 42.75,44.56 42.59,44.72 42.26,44.72 42.1,44.56 R152.1 ; U1.L5 v1(28.34,35.39)
  L7_SIGNAL w0.14: v1(43.23,27.57) 42.98,27.57 42.47,27.06 42.47,27.06 42.34,26.93 41.84,26.93 41.71,27.06 41.71,27.54 41.07,28.18 40.06,28.18 38.3,29.94 38.3,30.21 38.42,30.33 38.91,30.33 39.04,30.21 39.04,30.08 39.17,29.95 39.93,29.95 40.06,29.83 40.06,29.7 39.93,29.57 39.56,29.57 39.42,29.43 39.42,29.32 39.55,29.19 40.57,29.19 40.69,29.06 40.69,28.87 40.64,28.81 40.31,28.81 40.18,28.68 40.31,28.56 41.07,28.56 41.2,28.43 41.45,28.43 41.57,28.54 41.57,28.7 41.48,28.79 41.48,28.79 41.01,29.25 41.01,29.25 39.93,30.34 39.42,30.34 38.97,30.79 38.21,30.79 38.15,30.84 38.15,31.1 38.28,31.22 38.28,31.48 38.16,31.6 37.64,31.6 37.52,31.48 37.52,31.15 37.39,31.03 32.99,31.03 32.77,31.24 32.77,31.52 32.47,31.83 31.39,31.83 31.17,32.04 31.17,32.34 31.29,32.46 31.29,32.62 31.17,32.75 31.04,32.75 30.92,32.63 30.59,32.63 30.37,32.84 30.37,33.14 30.53,33.3 30.53,33.48 30.38,33.64 30.29,33.64 30.09,33.43 29.86,33.43 29.6,33.17 29.35,33.17 29.26,33.26 29.26,33.69 29.63,34.06 29.63,34.38 29.27,34.74 28.7,34.74 28.34,35.1 v1(28.34,35.39)
  L12_SIGNAL w0.14: v1(43.23,44.33) 43.2,44.3 42.91,44.3 42.58,43.97 42.13,43.97 41.84,43.67 41.84,33.64 43.61,31.86 43.61,30.64 43.3,30.33 43.08,30.33 42.86,30.12 42.86,27.93 v1(43.23,27.57)
  BOTTOM w0.197: U2.M2 v1(43.23,27.57) ; U3.M2 v1(43.23,44.33)
DDR3_BA1: length 52.9
  TOP w0.197: v1(48.83,45.13) 49.24,45.54 50,45.54 50.47,45.07 R153.1 ; U1.R4 v1(25.14,36.19)
  L7_SIGNAL w0.14: v1(48.83,28.3) 47.66,26.85 47.54,26.46 46.92,25.89 46.57,25.67 44.68,25.53 43.49,25.33 42.14,25.33 39.3,26.27 37.5,28.04 37.5,28.34 37.29,28.55 36.99,28.63 36.77,28.84 36.7,29.14 36.49,29.35 30.59,29.43 30.37,29.64 30.3,29.94 30.09,30.15 30.08,30.15 28.7,31.54 28.7,31.54 28.49,31.75 28.19,31.83 27.97,32.04 27.9,32.34 27.69,32.55 27.36,32.62 27.17,32.84 27.05,33.19 26.93,33.3 26.59,33.43 26.37,33.64 26.3,33.94 26.09,34.15 25.71,34.27 25.57,34.44 25.5,35.54 v1(25.14,36.19)
  L12_SIGNAL w0.14: v1(48.83,28.3) 49.24,28.71 49.24,30.09 49.27,30.12 49.27,30.92 49.84,31.49 49.84,32.24 47.63,34.44 47.63,43.94 v1(48.83,45.13)
  BOTTOM w0.197: U2.N8 48.76,28.3 v1(48.83,28.3) ; U3.N8 v1(48.83,45.13)
DDR3_BA2: length 54.3
  TOP w0.197: v1(44.03,44.33) 44.38,44.69 45.2,44.69 R154.1 ; U1.J5 v1(30.74,35.39)
  L7_SIGNAL w0.14: v1(30.74,35.39) 30.74,35.52 30.46,35.8 29.77,35.8 29.57,35.6 29.57,35.43 29.43,35.29 29.39,35.29 29.26,35.41 29.26,35.67 29.14,35.8 29,35.8 28.75,35.55 28.75,35.15 28.88,35.03 30.16,35.03 30.37,34.81 30.37,34.53 30.28,34.43 30.28,34.4 30.14,34.26 30.14,34.16 30.28,34.02 30.45,34.02 30.59,34.15 30.89,34.15 31.1,33.94 31.1,33.57 31.04,33.51 31.04,33.26 31.13,33.16 31.2,33.16 31.39,33.35 31.69,33.35 31.9,33.14 31.9,32.68 32.02,32.55 32.51,32.55 32.77,32.28 32.77,32.04 32.99,31.83 34.09,31.83 34.12,31.86 34.55,31.86 34.59,31.83 37.39,31.83 37.52,31.95 37.52,31.99 37.64,32.11 38.03,32.11 39.42,30.72 39.93,30.72 41.84,28.81 41.84,28.3 41.68,28.15 41.68,27.95 41.84,27.79 42.09,27.79 42.22,27.92 42.22,27.93 45.13,27.93 45.24,28.04 47.17,28.04 47.3,27.91 47.3,27.67 47.17,27.54 46.79,27.54 46.66,27.67 46.41,27.67 46.28,27.54 46.03,27.54 45.9,27.67 45.65,27.67 45.52,27.54 44.05,27.54 v1(44.03,27.57)
  L12_SIGNAL w0.14: v1(44.03,27.57) 44.88,28.42 44.88,33.51 44.5,33.89 44.5,40.37 43.99,40.88 43.74,40.88 42.85,41.76 42.85,43.67 43.08,43.89 43.33,43.89 43.36,43.92 43.62,43.92 v1(44.03,44.33)
  BOTTOM w0.197: U2.M3 v1(44.03,27.57) ; U3.M3 v1(44.03,44.33)
DDR3_CAS#: length 54.5
  TOP w0.197: v1(44.03,42.73) 44.33,43.03 45.33,43.03 R159.1 ; U1.P5 v1(25.94,35.39)
  L6_SIGNAL w0.14: v1(44.83,25.97) 44.83,26.25 46.29,27.72 46.29,33.75 46.28,33.76 46.28,37.83 46.15,37.95 44.51,37.95 44.39,38.08 44.39,42.08 44.38,42.09 44.38,42.38 v1(44.03,42.73)
  L7_SIGNAL w0.14: v1(44.83,25.97) 44.78,26.02 43.86,26.02 43.74,25.89 43.74,25.73 43.63,25.63 43.5,25.6 42.28,25.6 41.75,26.13 40.66,26.13 40.16,26.29 40.06,26.44 40.06,26.6 40.21,26.75 40.21,26.88 38.46,28.63 38.28,28.63 38.14,28.49 38.14,28.31 39.7,26.75 39.7,26.66 39.56,26.52 39.42,26.52 37.77,28.18 37.77,28.51 37.57,28.7 37.57,28.87 37.77,29.06 37.77,29.19 37.64,29.32 37.54,29.32 37.41,29.45 37.41,29.55 37.5,29.64 37.5,29.94 37.29,30.15 36.96,30.15 36.84,30.03 36.66,30.03 36.53,30.15 36.19,30.15 36.01,29.98 35.86,29.98 35.69,30.15 35.36,30.15 35.21,30.01 35.03,30.01 34.89,30.15 34.54,30.15 34.34,29.95 34.34,29.83 34.22,29.7 33.71,29.7 33.58,29.83 33.58,30.02 33.45,30.15 30.59,30.15 30.43,30.31 30.43,30.56 30.21,30.78 29.96,30.78 29.01,31.73 29.01,31.99 28.7,32.3 28.7,32.34 28.49,32.55 28.26,32.55 27.97,32.84 27.97,33.06 27.69,33.35 27.46,33.35 27.17,33.64 27.17,33.86 26.89,34.15 26.5,34.15 26.37,34.28 26.37,34.66 25.94,35.1 v1(25.94,35.39)
  BOTTOM w0.197: U3.K3 v1(44.03,42.73) ; U2.K3 v1(44.83,25.97)
DDR3_CK_N: length 59.4
  TOP w0.152: R142.2 49.39,42.46 48.29,42.46 v1(48.03,42.73) ; U1.M2 v1(27.54,37.79)
  L6_SIGNAL w0.13: v1(48.03,25.97) 47.75,25.69 47.63,25.69 47.35,25.97 47.35,32.69 47.56,32.9 49.41,32.9 50.24,33.73 50.24,40.58 50.22,40.6 50.22,41.94 48.97,43.19 48.48,43.19 48.14,42.85 v1(48.03,42.73)
  L13_SIGNAL w0.13: v1(27.54,37.79) 27.83,37.79 28.25,38.21 28.73,38.21 29.01,37.93 29.01,36.16 29.52,35.65 29.52,30.95 30,30.46 31.17,30.46 31.74,31.03 32.18,31.03 32.75,30.46 32.92,30.46 33.48,31.03 33.9,31.03 34.47,30.46 39.04,30.46 40.06,29.45 40.06,28.7 39.68,28.33 39.68,28.03 40.94,26.77 41.84,26.77 42.07,26.54 42.07,25.82 42.09,25.8 42.09,25.62 42.73,24.98 43.4,24.98 43.68,25.25 44.23,25.25 44.68,24.81 45.96,24.81 46.04,24.88 46.24,25.09 46.28,25.13 46.34,25.19 46.9,25.75 47.12,25.97 v1(48.03,25.97)
  BOTTOM w0.152: U2.K7 v1(48.03,25.97) ; U3.K7 v1(48.03,42.73)
DDR3_CK_P: length 60.3
  TOP w0.152: v1(48.03,41.93) 48.28,42.18 49.21,42.18 R142.1 ; U1.L2 v1(28.34,37.79)
  L6_SIGNAL w0.13: v1(48.03,41.93) 48.19,42.09 48.19,42.27 48.39,42.47 48.97,42.47 49,42.5 49.3,42.5 49.96,41.84 49.96,40.5 49.98,40.48 49.98,33.84 49.3,33.16 47.45,33.16 47.09,32.8 47.09,25.86 47.52,25.44 47.75,25.44 v1(48.03,25.17)
  L13_SIGNAL w0.13: v1(28.34,37.79) 28.5,37.95 28.63,37.95 28.75,37.83 28.75,36.05 29.26,35.54 29.26,30.84 29.9,30.21 31.28,30.21 31.84,30.78 32.07,30.78 32.64,30.21 33.02,30.21 33.59,30.78 33.79,30.78 34.36,30.21 38.93,30.21 39.8,29.34 39.8,28.81 39.42,28.43 39.42,27.92 40.83,26.51 41.74,26.51 41.81,26.44 41.81,25.71 41.83,25.69 41.83,25.51 42.62,24.72 43.51,24.72 43.78,25 44.13,25 44.57,24.55 46.07,24.55 46.22,24.7 46.46,24.95 46.69,24.95 47.12,24.52 47.3,24.52 47.45,24.67 47.45,24.85 47.07,25.23 47.07,25.55 47.23,25.71 47.68,25.71 47.81,25.58 47.81,25.38 v1(48.03,25.17)
  BOTTOM w0.152: U3.J7 v1(48.03,41.93) ; U2.J7 v1(48.03,25.17)
DDR3_CKE: length 58.2
  TOP w0.197: v1(48.83,41.82) 48.83,41.37 49.24,40.97 49.58,40.97 49.93,40.62 R160.1 ; U1.N3 v1(26.74,36.99)
  L7_SIGNAL w0.14: v1(49.63,25.97) 49.4,25.97 48.97,25.53 48.68,25.53 48.46,25.32 48.46,25.03 48.24,24.8 40,24.8 37.5,27.31 37.5,27.54 37.29,27.75 37.06,27.75 36.77,28.04 36.77,28.34 36.49,28.63 30.59,28.63 30.37,28.84 30.37,29.1 30.04,29.43 29.79,29.43 27.9,31.32 27.9,31.54 27.69,31.75 27.46,31.75 27.1,32.12 27.1,32.34 26.89,32.55 26.66,32.55 26.3,32.92 26.3,33.14 26.09,33.35 25.74,33.35 25.5,33.59 25.5,33.94 25.29,34.15 24.82,34.15 24.69,34.28 24.69,34.43 24.7,34.44 24.7,34.74 24.69,34.74 24.69,35.23 24.7,35.24 24.7,35.54 24.69,35.54 24.69,36.03 24.7,36.04 24.7,36.43 24.82,36.55 26.01,36.55 26.45,36.99 v1(26.74,36.99)
  L12_SIGNAL w0.14: v1(48.83,41.82) 48.83,42.15 48.96,42.27 50.6,42.27 50.98,41.89 50.98,39.99 50.47,39.48 50.47,27.79 49.63,26.95 v1(49.63,25.97)
  BOTTOM w0.197: U3.K9 48.83,41.94 v1(48.83,41.82) ; U2.K9 v1(49.63,25.97)
DDR3_CS#: length 57.8
  TOP w0.197: U1.N1 v1(26.74,38.59) ; v1(43.23,43.53) 43.21,43.54 R163.1
  L6_SIGNAL w0.14: v1(43.23,26.77) 42.86,27.13 42.86,27.72 43.09,27.94 43.38,27.94 43.59,28.15 43.59,28.37 43.88,28.66 44.1,28.66 45.45,30.02 45.45,31.67 42.82,34.3 42.28,34.3 41.89,34.69 41.89,42.7 42.35,43.16 42.73,43.16 43,43.43 43.13,43.43 v1(43.23,43.53)
  L13_SIGNAL w0.14: v1(26.74,38.59) 26.74,38.6 27.23,39.1 28.34,39.1 29.31,38.13 29.31,36.5 29.57,36.24 29.57,36.04 29.86,35.75 30.09,35.75 30.3,35.54 30.3,31.08 30.53,30.84 31.04,30.84 31.17,30.97 31.17,31.48 31.17,31.48 31.17,31.54 31.39,31.75 34.09,31.75 34.37,31.46 34.37,31.24 34.59,31.03 37.57,31.03 38.15,31.6 38.79,31.6 40.82,29.57 40.82,28.43 42.09,27.16 43.36,27.16 43.66,27.47 43.66,27.72 43.88,27.93 45.01,27.93 45.14,27.8 45.14,27.25 45.01,27.13 44.68,27.13 44.46,26.92 44.46,26.71 44.15,26.4 43.59,26.4 v1(43.23,26.77)
  BOTTOM w0.197: U2.L2 v1(43.23,26.77) ; U3.L2 v1(43.23,43.53)
DDR3_DM0: length 30.3
  TOP w0.197: U1.A1 v1(37.14,38.59)
  L12_SIGNAL w0.14: v1(37.14,38.59) 37.14,38.84 37.26,38.97 40.58,38.97 40.7,38.84 40.7,34.16 40.97,33.9 40.97,32.22 41.96,31.22 41.96,25.76 42.22,25.51 43.97,25.51 44.73,24.75 47.55,24.75 47.68,24.62 47.68,23.71 47.55,23.58 47.3,23.58 47.17,23.46 47.17,20.81 47.3,20.68 47.83,20.68 48.03,20.88 v1(48.03,21.17)
  BOTTOM w0.197: U2.E7 v1(48.03,21.17)
DDR3_DM1: length 32.7
  TOP w0.197: U1.F1 v1(33.14,38.59)
  L12_SIGNAL w0.14: v1(33.14,38.59) 33.5,38.95 34.09,38.95 34.3,38.74 34.3,38.56 34.37,38.48 34.37,38.44 34.59,38.23 34.63,38.23 34.71,38.15 34.89,38.15 35.1,37.94 35.1,37.56 34.96,37.43 33.69,37.43 33.57,37.31 33.57,36.84 33.86,36.55 34.09,36.55 34.3,36.34 34.3,36.04 34.26,36 34.26,35.57 34.3,35.54 34.3,31.32 34.37,31.24 35.04,30.58 35.34,30.58 35.97,29.94 35.97,29.64 36.19,29.43 36.41,29.43 36.77,29.06 36.77,28.84 36.99,28.63 37.29,28.63 37.34,28.68 37.48,28.68 39.09,30.29 39.59,30.29 40.3,29.59 40.3,27.78 40.19,27.67 40.19,27.15 40.3,27.05 40.3,26.38 39.68,25.76 39.68,24.07 42.22,21.53 43.4,21.53 44.03,20.9 v1(44.03,20.37)
  BOTTOM w0.197: U2.D3 v1(44.03,20.37)
DDR3_DM2: length 30.5
  TOP w0.197: U1.T1 v1(24.34,38.59)
  L15_SIGNAL w0.14: v1(48.03,37.87) 47.94,37.95 47.55,37.95 47.3,38.21 47.3,39.73 47.17,39.86 46.41,39.86 46.28,39.73 46.28,38.46 45.77,37.95 45.01,37.95 44.69,37.63 42.64,37.63 42.58,37.57 40.19,37.57 38.28,39.48 30.78,39.48 30.64,39.33 30.41,39.33 30.27,39.48 27.22,39.48 27.1,39.35 27.1,38.44 26.81,38.15 24.77,38.15 v1(24.34,38.59)
  BOTTOM w0.197: v1(48.03,37.87) 48.03,37.93 U3.E7
DDR3_DM3: length 30.3
  TOP w0.197: U1.Y1 v1(21.14,38.59)
  L7_SIGNAL w0.14: v1(44.03,37.07) 42.72,38.37 42.28,38.37 42.06,38.58 42.06,39.03 40.34,40.75 38.69,42.4 30.78,42.4 30.64,42.54 30.64,42.64 30.5,42.78 30.22,42.78 30.08,42.64 30.08,42.54 29.94,42.4 29.66,42.4 29.52,42.54 29.52,42.78 29.4,42.91 29.09,42.91 28.96,42.78 28.96,42.54 28.82,42.4 28.55,42.4 28.41,42.54 28.41,42.64 28.27,42.78 27.99,42.78 27.85,42.64 27.85,42.54 27.71,42.4 25.96,42.4 24.31,40.75 22.28,40.75 21.14,39.61 v1(21.14,38.59)
  BOTTOM w0.197: U3.D3 44.03,37.13 v1(44.03,37.07)
DDR3_DQ0: length 30.5
  TOP w0.197: U1.C3 v1(35.54,36.99)
  L6_SIGNAL w0.14: v1(35.54,36.99) 35.56,36.99 35.97,36.58 35.97,32.84 36.19,32.63 36.37,32.63 36.44,32.55 37.29,32.55 38.43,31.41 38.43,27.77 39.04,27.16 39.04,23.35 41.59,20.8 43.86,20.8 44.63,21.57 47.42,21.57 47.55,21.44 47.55,20.76 47.42,20.63 45.36,20.63 v1(44.83,21.17)
  BOTTOM w0.197: U2.E3 v1(44.83,21.17)
DDR3_DQ1: length 30.3
  TOP w0.197: v1(36.34,36.99) U1.B3
  L16_SIGNAL w0.14: v1(48.03,21.97) 48.03,21.98 47.17,22.84 46.15,22.84 45.65,22.33 42.34,22.33 41.96,22.71 41.96,25.51 39.42,28.05 39.42,28.68 39.68,28.94 41.71,28.94 41.84,29.06 41.84,31.35 41.71,31.48 39.68,31.48 39.42,31.73 39.42,36.18 39.04,36.56 36.76,36.56 36.34,36.98 v1(36.34,36.99)
  BOTTOM w0.197: U2.F7 v1(48.03,21.97)
DDR3_DQ2: length 30.4
  TOP w0.197: U1.A2 v1(37.14,37.79)
  L6_SIGNAL w0.14: v1(37.14,37.79) 36.77,38.15 36.19,38.15 35.97,38.36 35.97,38.74 36.43,39.2 37.8,39.2 38.48,38.52 38.48,36.18 38.36,36.05 38.07,36.05 37.94,36.18 37.94,38.24 37.84,38.34 37.64,38.34 37.52,38.21 37.52,33.78 37.78,33.51 37.78,32.86 38.96,31.69 38.96,28.26 41.04,26.18 41.04,23.65 42.28,22.4 42.79,22.4 v1(43.23,21.97)
  BOTTOM w0.197: U2.F2 v1(43.23,21.97)
DDR3_DQ3: length 30.2
  TOP w0.197: U1.A4 v1(37.14,36.19)
  L16_SIGNAL w0.14: v1(37.14,36.19) 38.9,36.19 39.04,36.05 39.04,31.35 39.3,31.1 41.33,31.1 41.45,30.97 41.45,29.57 41.33,29.45 39.3,29.45 39.04,29.19 39.04,27.41 41.45,25 41.45,22.08 41.96,21.57 48.43,21.57 v1(48.83,21.97)
  BOTTOM w0.197: U2.F8 v1(48.83,21.97)
DDR3_DQ4: length 30.3
  TOP w0.197: U1.D3 v1(34.74,36.99)
  L6_SIGNAL w0.14: v1(44.83,23.57) 45.3,23.1 46.15,23.1 46.28,22.97 46.28,22.46 46.15,22.33 44.5,22.33 44.38,22.46 44.38,22.59 44.25,22.71 43.87,22.71 43.74,22.59 43.74,21.7 43.61,21.57 42.09,21.57 39.42,24.24 39.42,27.29 38.69,28.02 38.69,31.58 38.54,31.73 38.53,31.73 37.52,32.75 37.52,33.26 37.39,33.38 37.01,33.38 36.76,33.64 36.76,37.17 36.5,37.43 36.17,37.43 35.9,37.7 35.9,37.94 35.61,38.23 35.39,38.23 35.1,37.94 35.1,37.64 34.97,37.51 34.97,37.43 34.74,37.19 v1(34.74,36.99)
  BOTTOM w0.197: U2.H3 v1(44.83,23.57)
DDR3_DQ5: length 30.2
  TOP w0.197: v1(34.74,38.59) 34.74,38.58 34.34,38.19 U1.D1
  L6_SIGNAL w0.14: v1(48.83,23.57) 48.46,23.2 47.57,23.2 46.41,24.37 43.99,24.37 43.23,25.13 42.22,25.13 41.57,25.78 41.57,29.84 40.82,30.59 39.8,30.59 39.55,30.84 39.55,32.65 39.42,32.77 39.14,32.77 39.02,32.9 39.02,39.12 38.41,39.73 35.1,39.73 34.74,39.36 v1(34.74,38.59)
  BOTTOM w0.197: U2.H8 v1(48.83,23.57)
DDR3_DQ6: length 30.4
  TOP w0.197: U1.C1 v1(35.54,38.59)
  L6_SIGNAL w0.14: v1(35.54,38.59) 35.54,39.2 35.8,39.47 37.91,39.47 38.75,38.63 38.75,35.5 38.05,34.8 38.05,32.98 39.23,31.8 39.23,28.5 39.42,28.3 40.57,28.3 40.69,28.43 40.69,29.19 40.57,29.32 40.06,29.32 39.93,29.45 39.93,29.7 40.18,29.95 41.05,29.95 41.3,29.7 41.3,24.52 41.72,24.1 42.74,24.1 42.85,23.98 43.49,23.98 43.59,23.88 43.59,23.13 v1(43.23,22.77)
  BOTTOM w0.197: U2.G2 v1(43.23,22.77)
DDR3_DQ7: length 30.6
  TOP w0.197: U1.E1 v1(33.94,38.59)
  L6_SIGNAL w0.14: v1(33.94,38.59) 33.94,39.33 34.72,40.11 38.41,40.11 39.28,39.24 39.28,33.33 41.14,31.48 41.14,31.03 41.84,30.33 41.84,25.89 42.22,25.51 43.49,25.51 44.25,24.75 48.19,24.75 48.31,24.62 48.31,23.69 48.19,23.57 v1(48.03,23.57)
  BOTTOM w0.197: U2.H7 v1(48.03,23.57)
DDR3_DQ8: length 33.1
  TOP w0.197: U1.E2 v1(33.94,37.79)
  L6_SIGNAL w0.14: v1(48.03,20.37) 48.34,20.68 49.07,20.68 49.21,20.55 49.21,20.05 49.11,19.95 47.08,19.95 47.05,19.93 41.96,19.93 40.29,21.59 40.29,21.72 40.08,21.93 39.82,21.93 38.41,23.35 38.41,27.29 38.16,27.54 38.16,31.09 37.5,31.75 35.46,31.75 35.17,32.04 35.17,35.6 35.1,35.67 34.95,35.83 34.59,35.83 34.37,36.04 34.37,37.41 34.34,37.45 34,37.79 v1(33.94,37.79)
  BOTTOM w0.197: U2.D7 v1(48.03,20.37)
DDR3_DQ9: length 32.9
  TOP w0.197: U1.E3 v1(33.94,36.99)
  L12_SIGNAL w0.14: v1(44.83,20.37) 45.26,20.8 45.26,21.32 45.48,21.53 45.73,21.53 45.89,21.37 46.08,21.37 46.17,21.46 46.17,21.49 46.15,21.5 46.15,22.84 46.03,22.97 45.52,22.97 45.39,22.84 45.39,21.95 45.01,21.57 44.25,21.57 44.12,21.7 43.99,21.7 43.59,22.11 43.59,22.12 43.38,22.33 41.84,22.33 40.57,23.6 40.57,27.16 40.46,27.26 40.46,27.56 40.57,27.67 40.57,29.83 39.42,30.97 38.79,30.97 38.53,30.72 38.53,30.46 37.5,29.43 36.99,29.43 36.77,29.64 36.77,29.88 36.39,30.27 36.35,30.27 35.77,30.84 35.3,30.84 35.1,31.04 35.1,36.18 35.1,36.18 35.1,36.34 34.89,36.55 34.66,36.55 34.22,36.99 v1(33.94,36.99)
  BOTTOM w0.197: U2.C3 v1(44.83,20.37)
DDR3_DQ10: length 33
  TOP w0.197: U1.G3 v1(32.34,36.99)
  L12_SIGNAL w0.14: v1(48.83,19.59) 48.46,19.95 47.08,19.95 47.04,19.92 44.98,19.92 44.98,19.93 44.68,19.93 44.67,19.92 43.87,19.92 43.66,20.12 43.66,20.5 43.44,20.73 42.34,20.73 40.46,22.61 39.91,22.61 39.7,22.82 39.7,23.37 39.41,23.66 39.41,25.87 39.92,26.39 39.92,28.18 39.3,28.81 38.27,28.81 37.29,27.83 36.99,27.83 36.77,28.04 36.77,28.34 36.49,28.63 36.19,28.63 35.97,28.84 35.97,29.14 35.69,29.43 35.39,29.43 35.17,29.64 35.17,29.88 34.03,31.03 33.79,31.03 33.5,31.32 33.5,36.34 33.28,36.55 32.95,36.55 32.51,36.99 v1(32.34,36.99)
  BOTTOM w0.197: v1(48.83,19.59) 48.8,19.59 U2.C8
DDR3_DQ11: length 32.7
  TOP w0.197: U1.H3 v1(31.54,36.99)
  L12_SIGNAL w0.14: v1(31.54,36.99) 31.54,36.7 31.68,36.55 31.69,36.55 31.9,36.34 31.9,36.34 31.93,36.3 31.93,31.22 31.55,30.84 31.55,30.59 31.68,30.46 32.06,30.46 32.37,30.15 32.63,30.15 32.97,30.49 33.17,30.49 33.58,30.08 33.58,29.22 33.5,29.14 33.5,28.92 33.79,28.63 34.98,28.63 35.1,28.5 35.1,27.55 35.1,27.54 35.1,27.32 35.39,27.03 35.61,27.03 35.9,26.74 35.9,26.52 36.19,26.23 37.29,26.23 37.5,26.44 37.5,26.61 37.64,26.76 38.42,26.76 38.66,26.52 38.66,23.1 39.8,21.95 40.18,21.95 40.31,21.83 40.31,21.44 40.52,21.23 41.08,21.23 42.06,20.25 42.06,19.42 42.32,19.16 42.6,19.16 42.86,18.89 42.86,18.62 43.08,18.4 43.58,18.4 43.77,18.59 44.06,18.59 44.25,18.78 44.25,19.16 44.12,19.29 43.51,19.29 v1(43.23,19.57)
  BOTTOM w0.197: U2.C2 v1(43.23,19.57)
DDR3_DQ12: length 32.9
  TOP w0.197: U1.J3 v1(30.74,36.99)
  L12_SIGNAL w0.14: v1(48.03,17.91) 48,17.94 48,17.95 47.62,18.33 43.88,18.33 43.66,18.12 43.66,17.94 43.59,17.86 43.59,17.82 43.38,17.6 41.99,17.6 39.42,20.17 37.52,23.48 37.5,23.5 37.5,23.54 37.29,23.75 37.06,23.75 36.77,24.04 36.77,24.26 36.41,24.63 36.19,24.63 35.9,24.92 35.9,25.14 35.61,25.43 35.39,25.43 35.1,25.72 35.1,25.94 34.81,26.23 34.59,26.23 34.3,26.52 34.3,26.74 34.01,27.03 33.79,27.03 33.5,27.32 33.5,27.54 33.21,27.83 32.99,27.83 32.7,28.12 32.7,28.34 32.41,28.63 32.19,28.63 31.9,28.92 31.9,29.14 31.61,29.43 31.39,29.43 31.1,29.72 31.1,29.94 30.89,30.15 30.3,30.95 30.3,36.55 v1(30.74,36.99)
  BOTTOM w0.197: v1(48.03,17.91) 48.03,17.97 U2.A7
DDR3_DQ13: length 32.9
  TOP w0.197: U1.H2 v1(31.54,37.79)
  L12_SIGNAL w0.14: v1(43.23,17.97) 43.03,17.97 42.6,18.4 42.09,18.4 41.71,18.78 41.71,20.05 40.82,20.94 39.93,20.94 39.3,21.57 39.3,21.95 38.39,22.85 38.39,26.02 38.27,26.14 37.77,26.14 37.64,26.02 37.64,25 37.9,24.75 37.9,24.1 37.78,23.98 37.61,23.98 37.5,24.1 37.5,24.34 37.21,24.63 36.99,24.63 36.7,24.92 36.7,25.14 36.41,25.43 36.19,25.43 35.9,25.72 35.9,25.94 35.61,26.23 35.39,26.23 35.1,26.52 35.1,26.74 34.81,27.03 34.59,27.03 34.3,27.32 34.3,27.54 34.01,27.83 33.79,27.83 33.5,28.12 33.5,28.34 33.21,28.63 32.99,28.63 32.7,28.92 32.7,29.14 32.41,29.43 32.19,29.43 31.9,29.72 31.9,29.94 31.69,30.15 31.61,30.15 31.17,30.59 31.17,37.32 31.54,37.69 v1(31.54,37.79)
  BOTTOM w0.197: U2.A2 v1(43.23,17.97)
